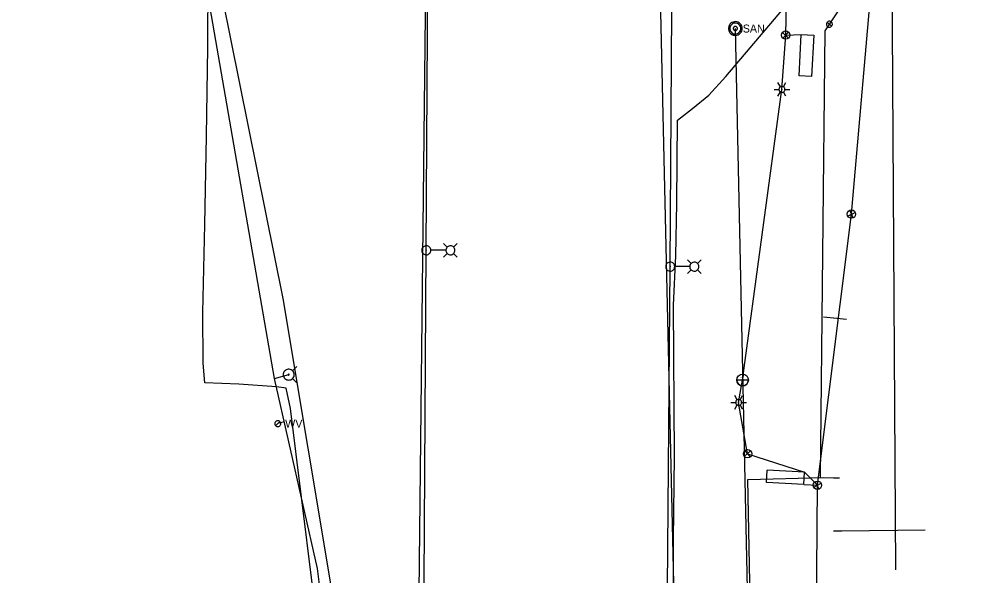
# Model space of a CAD drawing. Extents: x 600849 to 606371, y 330010 to 403088.
# Drawn here: x 604685.3 to 605141.7, y 332364 to 332631.5 of the extents above; entities that cross this region are included whole.
import ezdxf

# ---------------------------------------------------------------- set-up
doc = ezdxf.new("R2010")
doc.units = 0
for name, color, linetype in [('E_FTMS_Conduit', 7, 'Continuous'), ('E_LTG', 7, 'Continuous'), ('E_LTG_CID', 7, 'Continuous'), ('E_SIG', 7, 'Continuous'), ('E_SIG_Conduit', 7, 'Continuous'), ('E_UTL_E_UG', 7, 'Continuous'), ('E_UTL_G_UG', 7, 'Continuous'), ('E_UTL_Loop_UG', 7, 'Continuous'), ('E_UTL_SAN', 7, 'Continuous'), ('E_UTL_SAN_UG', 7, 'Continuous'), ('E_UTL_SAN_UG_MMSD', 7, 'Continuous'), ('E_UTL_W', 7, 'Continuous'), ('E_UTL_W_UG', 7, 'Continuous'), ('E_UTL_WHydrant', 7, 'Continuous')]:
    doc.layers.add(name, color=color, linetype=linetype)

# ---------------------------------------------------------------- blocks, each defined once
blk = doc.blocks.new('_U297')
at = {"layer": 'E_LTG'}
blk.add_lwpolyline([(0.001, -0.171), (0.001, 0.172)], dxfattribs=at)
blk.add_circle((0.001, 0), 0.171, dxfattribs=at)
blk.add_arc((0.001, 0), 0.171, 90, 270, dxfattribs=at)
blk.add_text('L', height=0.108, dxfattribs=at).set_placement((0.066, -0.042))
blk = doc.blocks.new('_U298')
at = {"layer": 'E_SIG'}
for p, q in [((-6.1, 0.4), (6.1, 0.4)), ((0, 6.1), (0, -6.1))]:
    blk.add_line(p, q, dxfattribs=at)
blk.add_circle((0, 0), 6.1, dxfattribs=at)
blk = doc.blocks.new('_U311')
at = {"layer": 'E_SIG'}
for p, q in [((-6.1, 0.4), (6.1, 0.4)), ((0, 6.1), (0, -6.1))]:
    blk.add_line(p, q, dxfattribs=at)
blk.add_circle((0, 0), 6.1, dxfattribs=at)
blk = doc.blocks.new('_U312')
at = {"layer": 'E_SIG'}
for p, q in [((-6.1, 0.4), (6.1, 0.4)), ((0, 6.1), (0, -6.1))]:
    blk.add_line(p, q, dxfattribs=at)
blk.add_circle((0, 0), 6.1, dxfattribs=at)
blk = doc.blocks.new('_U313')
at = {"layer": 'E_SIG'}
for p, q in [((-6.1, 0.4), (6.1, 0.4)), ((0, 6.1), (0, -6.1))]:
    blk.add_line(p, q, dxfattribs=at)
blk.add_circle((0, 0), 6.1, dxfattribs=at)

msp = doc.modelspace()

# ---------------------------------------------------------------- linework, layer by layer
at = {"layer": 'E_FTMS_Conduit'}
msp.add_lwpolyline([(604875.48, 332151.89), (604882.43, 332779.77)], dxfattribs=at)
at = {"layer": 'E_LTG'}
for points in [[(605051.51, 332598.97), (605050.32, 332601.03)], [(605052.94, 332598.97), (605054.13, 332601.03)], [(605048.42, 332597.73), (605050.8, 332597.73)], [(605050.32, 332594.43), (605051.51, 332596.49)], [(605053.66, 332597.73), (605053.63, 332598), (605053.55, 332598.26), (605053.43, 332598.5), (605053.26, 332598.72), (605053.06, 332598.89), (605052.82, 332599.03), (605052.56, 332599.12), (605052.29, 332599.16), (605052.02, 332599.15), (605051.76, 332599.08), (605051.51, 332598.97), (605051.29, 332598.81), (605051.1, 332598.61), (605050.96, 332598.39), (605050.86, 332598.13), (605050.8, 332597.87), (605050.8, 332597.59), (605050.86, 332597.33), (605050.96, 332597.08), (605051.1, 332596.85), (605051.29, 332596.65), (605051.51, 332596.49), (605051.76, 332596.38), (605052.02, 332596.32), (605052.29, 332596.3), (605052.56, 332596.34), (605052.82, 332596.43), (605053.06, 332596.57), (605053.26, 332596.74), (605053.43, 332596.96), (605053.55, 332597.2), (605053.63, 332597.46), (605053.66, 332597.73)], [(605053.66, 332597.73), (605053.63, 332598), (605053.55, 332598.26), (605053.43, 332598.5), (605053.26, 332598.72), (605053.06, 332598.89), (605052.82, 332599.03), (605052.56, 332599.12), (605052.29, 332599.16), (605052.02, 332599.15), (605051.76, 332599.08), (605051.51, 332598.97), (605051.29, 332598.81), (605051.1, 332598.61), (605050.96, 332598.39), (605050.86, 332598.13), (605050.8, 332597.87), (605050.8, 332597.59), (605050.86, 332597.33), (605050.96, 332597.08), (605051.1, 332596.85), (605051.29, 332596.65), (605051.51, 332596.49), (605051.76, 332596.38), (605052.02, 332596.32), (605052.29, 332596.3), (605052.56, 332596.34), (605052.82, 332596.43), (605053.06, 332596.57), (605053.26, 332596.74), (605053.43, 332596.96), (605053.55, 332597.2), (605053.63, 332597.46), (605053.66, 332597.73)], [(605053.66, 332597.73), (605053.63, 332598), (605053.55, 332598.26), (605053.43, 332598.5), (605053.26, 332598.72), (605053.06, 332598.89), (605052.82, 332599.03), (605052.56, 332599.12), (605052.29, 332599.16), (605052.02, 332599.15), (605051.76, 332599.08), (605051.51, 332598.97), (605051.29, 332598.81), (605051.1, 332598.61), (605050.96, 332598.39), (605050.86, 332598.13), (605050.8, 332597.87), (605050.8, 332597.59), (605050.86, 332597.33), (605050.96, 332597.08), (605051.1, 332596.85), (605051.29, 332596.65), (605051.51, 332596.49), (605051.76, 332596.38), (605052.02, 332596.32), (605052.29, 332596.3), (605052.56, 332596.34), (605052.82, 332596.43), (605053.06, 332596.57), (605053.26, 332596.74), (605053.43, 332596.96), (605053.55, 332597.2), (605053.63, 332597.46), (605053.66, 332597.73)], [(605052.35, 332597.73), (605052.34, 332597.75), (605052.34, 332597.78), (605052.33, 332597.8), (605052.31, 332597.81), (605052.3, 332597.83), (605052.28, 332597.84), (605052.25, 332597.85), (605052.23, 332597.85), (605052.21, 332597.85), (605052.19, 332597.84), (605052.17, 332597.83), (605052.15, 332597.82), (605052.13, 332597.8), (605052.12, 332597.79), (605052.11, 332597.76), (605052.11, 332597.74), (605052.11, 332597.72), (605052.11, 332597.7), (605052.12, 332597.68), (605052.13, 332597.66), (605052.15, 332597.64), (605052.17, 332597.63), (605052.19, 332597.62), (605052.21, 332597.61), (605052.23, 332597.61), (605052.25, 332597.62), (605052.28, 332597.62), (605052.3, 332597.63), (605052.31, 332597.65), (605052.33, 332597.67), (605052.34, 332597.69), (605052.34, 332597.71), (605052.35, 332597.73)], [(605054.13, 332594.43), (605052.94, 332596.49)], [(605053.66, 332597.73), (605056.04, 332597.73)], [(604883.39, 332520.43), (604883.35, 332520.85), (604883.23, 332521.24), (604883.04, 332521.61), (604882.78, 332521.94), (604882.47, 332522.21), (604882.11, 332522.41), (604881.72, 332522.55), (604881.31, 332522.61), (604880.9, 332522.59), (604880.5, 332522.49), (604880.12, 332522.32), (604879.79, 332522.08), (604879.5, 332521.78), (604879.28, 332521.43), (604879.12, 332521.05), (604879.04, 332520.64), (604879.04, 332520.23), (604879.12, 332519.82), (604879.28, 332519.44), (604879.5, 332519.09), (604879.79, 332518.79), (604880.12, 332518.55), (604880.5, 332518.38), (604880.9, 332518.28), (604881.31, 332518.26), (604881.72, 332518.32), (604882.11, 332518.45), (604882.47, 332518.66), (604882.78, 332518.93), (604883.04, 332519.26), (604883.23, 332519.63), (604883.35, 332520.02), (604883.39, 332520.43)], [(604891.29, 332521.96), (604889.51, 332523.73)], [(604894.99, 332520.43), (604894.95, 332520.85), (604894.83, 332521.24), (604894.64, 332521.61), (604894.39, 332521.94), (604894.08, 332522.21), (604893.72, 332522.41), (604893.33, 332522.55), (604892.92, 332522.61), (604892.5, 332522.59), (604892.1, 332522.49), (604891.73, 332522.32), (604891.39, 332522.08), (604891.1, 332521.78), (604890.88, 332521.43), (604890.73, 332521.05), (604890.65, 332520.64), (604890.65, 332520.23), (604890.73, 332519.82), (604890.88, 332519.44), (604891.1, 332519.09), (604891.39, 332518.79), (604891.73, 332518.55), (604892.1, 332518.38), (604892.5, 332518.28), (604892.92, 332518.26), (604893.33, 332518.32), (604893.72, 332518.45), (604894.08, 332518.66), (604894.39, 332518.93), (604894.64, 332519.26), (604894.83, 332519.63), (604894.95, 332520.02), (604894.99, 332520.43)], [(604894.34, 332521.96), (604896.11, 332523.73)], [(604881.38, 332520.43), (604881.37, 332520.47), (604881.36, 332520.5), (604881.35, 332520.52), (604881.33, 332520.55), (604881.31, 332520.57), (604881.28, 332520.59), (604881.25, 332520.6), (604881.22, 332520.6), (604881.19, 332520.6), (604881.16, 332520.59), (604881.13, 332520.58), (604881.1, 332520.56), (604881.08, 332520.54), (604881.06, 332520.51), (604881.05, 332520.48), (604881.04, 332520.45), (604881.04, 332520.42), (604881.05, 332520.39), (604881.06, 332520.36), (604881.08, 332520.33), (604881.1, 332520.31), (604881.13, 332520.29), (604881.16, 332520.28), (604881.19, 332520.27), (604881.22, 332520.27), (604881.25, 332520.27), (604881.28, 332520.28), (604881.31, 332520.3), (604881.33, 332520.32), (604881.35, 332520.34), (604881.36, 332520.37), (604881.37, 332520.4), (604881.38, 332520.43)], [(604890.6, 332520.43), (604883.42, 332520.43)], [(604891.29, 332518.91), (604889.51, 332517.13)], [(604894.34, 332518.91), (604896.11, 332517.13)], [(605000.66, 332512.59), (605000.62, 332513), (605000.51, 332513.4), (605000.32, 332513.77), (605000.06, 332514.09), (604999.75, 332514.36), (604999.39, 332514.57), (604999, 332514.71), (604998.59, 332514.76), (604998.18, 332514.74), (604997.78, 332514.65), (604997.4, 332514.48), (604997.06, 332514.24), (604996.78, 332513.94), (604996.55, 332513.59), (604996.4, 332513.2), (604996.32, 332512.8), (604996.32, 332512.38), (604996.4, 332511.98), (604996.55, 332511.59), (604996.78, 332511.25), (604997.06, 332510.95), (604997.4, 332510.71), (604997.78, 332510.53), (604998.18, 332510.44), (604998.59, 332510.42), (604999, 332510.48), (604999.39, 332510.61), (604999.75, 332510.82), (605000.06, 332511.09), (605000.32, 332511.41), (605000.51, 332511.78), (605000.62, 332512.18), (605000.66, 332512.59)], [(605008.57, 332514.12), (605006.79, 332515.89)], [(605012.27, 332512.59), (605012.23, 332513), (605012.11, 332513.4), (605011.92, 332513.77), (605011.66, 332514.09), (605011.35, 332514.36), (605010.99, 332514.57), (605010.6, 332514.71), (605010.19, 332514.76), (605009.78, 332514.74), (605009.38, 332514.65), (605009, 332514.48), (605008.67, 332514.24), (605008.38, 332513.94), (605008.16, 332513.59), (605008, 332513.2), (605007.92, 332512.8), (605007.92, 332512.38), (605008, 332511.98), (605008.16, 332511.59), (605008.38, 332511.25), (605008.67, 332510.95), (605009, 332510.71), (605009.38, 332510.53), (605009.78, 332510.44), (605010.19, 332510.42), (605010.6, 332510.48), (605010.99, 332510.61), (605011.35, 332510.82), (605011.66, 332511.09), (605011.92, 332511.41), (605012.11, 332511.78), (605012.23, 332512.18), (605012.27, 332512.59)], [(605011.62, 332514.12), (605013.39, 332515.89)], [(604998.65, 332512.59), (604998.65, 332512.62), (604998.64, 332512.65), (604998.63, 332512.68), (604998.61, 332512.71), (604998.58, 332512.73), (604998.56, 332512.74), (604998.53, 332512.75), (604998.49, 332512.76), (604998.46, 332512.76), (604998.43, 332512.75), (604998.4, 332512.74), (604998.38, 332512.72), (604998.36, 332512.69), (604998.34, 332512.67), (604998.33, 332512.64), (604998.32, 332512.61), (604998.32, 332512.58), (604998.33, 332512.54), (604998.34, 332512.51), (604998.36, 332512.49), (604998.38, 332512.47), (604998.4, 332512.45), (604998.43, 332512.43), (604998.46, 332512.43), (604998.49, 332512.42), (604998.53, 332512.43), (604998.56, 332512.44), (604998.58, 332512.46), (604998.61, 332512.48), (604998.63, 332512.5), (604998.64, 332512.53), (604998.65, 332512.56), (604998.65, 332512.59)], [(605007.88, 332512.59), (605000.7, 332512.59)], [(605008.57, 332511.07), (605006.79, 332509.29)], [(605011.62, 332511.07), (605013.39, 332509.29)], [(605030.68, 332448.61), (605029.49, 332450.67)], [(605032.11, 332448.61), (605033.3, 332450.67)], [(605027.58, 332447.37), (605029.96, 332447.37)], [(605029.49, 332444.07), (605030.68, 332446.13)], [(605032.82, 332447.37), (605032.8, 332447.64), (605032.72, 332447.9), (605032.6, 332448.14), (605032.43, 332448.35), (605032.22, 332448.53), (605031.99, 332448.67), (605031.73, 332448.76), (605031.46, 332448.8), (605031.19, 332448.78), (605030.93, 332448.72), (605030.68, 332448.61), (605030.46, 332448.45), (605030.27, 332448.25), (605030.12, 332448.02), (605030.02, 332447.77), (605029.97, 332447.5), (605029.97, 332447.23), (605030.02, 332446.97), (605030.12, 332446.71), (605030.27, 332446.48), (605030.46, 332446.29), (605030.68, 332446.13), (605030.93, 332446.02), (605031.19, 332445.95), (605031.46, 332445.94), (605031.73, 332445.98), (605031.99, 332446.07), (605032.22, 332446.2), (605032.43, 332446.38), (605032.6, 332446.6), (605032.72, 332446.84), (605032.8, 332447.1), (605032.82, 332447.37)], [(605032.82, 332447.37), (605032.8, 332447.64), (605032.72, 332447.9), (605032.6, 332448.14), (605032.43, 332448.35), (605032.22, 332448.53), (605031.99, 332448.67), (605031.73, 332448.76), (605031.46, 332448.8), (605031.19, 332448.78), (605030.93, 332448.72), (605030.68, 332448.61), (605030.46, 332448.45), (605030.27, 332448.25), (605030.12, 332448.02), (605030.02, 332447.77), (605029.97, 332447.5), (605029.97, 332447.23), (605030.02, 332446.97), (605030.12, 332446.71), (605030.27, 332446.48), (605030.46, 332446.29), (605030.68, 332446.13), (605030.93, 332446.02), (605031.19, 332445.95), (605031.46, 332445.94), (605031.73, 332445.98), (605031.99, 332446.07), (605032.22, 332446.2), (605032.43, 332446.38), (605032.6, 332446.6), (605032.72, 332446.84), (605032.8, 332447.1), (605032.82, 332447.37)], [(605032.82, 332447.37), (605032.8, 332447.64), (605032.72, 332447.9), (605032.6, 332448.14), (605032.43, 332448.35), (605032.22, 332448.53), (605031.99, 332448.67), (605031.73, 332448.76), (605031.46, 332448.8), (605031.19, 332448.78), (605030.93, 332448.72), (605030.68, 332448.61), (605030.46, 332448.45), (605030.27, 332448.25), (605030.12, 332448.02), (605030.02, 332447.77), (605029.97, 332447.5), (605029.97, 332447.23), (605030.02, 332446.97), (605030.12, 332446.71), (605030.27, 332446.48), (605030.46, 332446.29), (605030.68, 332446.13), (605030.93, 332446.02), (605031.19, 332445.95), (605031.46, 332445.94), (605031.73, 332445.98), (605031.99, 332446.07), (605032.22, 332446.2), (605032.43, 332446.38), (605032.6, 332446.6), (605032.72, 332446.84), (605032.8, 332447.1), (605032.82, 332447.37)], [(605031.51, 332447.37), (605031.51, 332447.39), (605031.5, 332447.41), (605031.49, 332447.43), (605031.48, 332447.45), (605031.46, 332447.47), (605031.44, 332447.48), (605031.42, 332447.48), (605031.4, 332447.49), (605031.38, 332447.49), (605031.35, 332447.48), (605031.33, 332447.47), (605031.32, 332447.46), (605031.3, 332447.44), (605031.29, 332447.42), (605031.28, 332447.4), (605031.28, 332447.38), (605031.28, 332447.36), (605031.28, 332447.33), (605031.29, 332447.31), (605031.3, 332447.29), (605031.32, 332447.28), (605031.33, 332447.26), (605031.35, 332447.26), (605031.38, 332447.25), (605031.4, 332447.25), (605031.42, 332447.25), (605031.44, 332447.26), (605031.46, 332447.27), (605031.48, 332447.29), (605031.49, 332447.3), (605031.5, 332447.32), (605031.51, 332447.35), (605031.51, 332447.37)], [(605033.3, 332444.07), (605032.11, 332446.13)], [(605032.82, 332447.37), (605035.2, 332447.37)]]:
    msp.add_lwpolyline(points, dxfattribs=at)
at = {"layer": 'E_LTG_CID'}
for points in [[(604879.6, 332255.02), (604881.21, 332520.43), (604882.73, 332780.27), (604878.2, 332790.52), (604877.91, 332791.78), (604881.34, 332802.26), (604883.13, 332854.03), (604882.52, 332888.97), (604884.51, 332915.54), (604885.08, 332965.87), (604885.55, 333001.94), (604887.55, 333053.11), (604887.38, 333057.43), (604890.09, 333114.03), (604893.58, 333149.05), (604892.31, 333167.75), (604894.55, 333225.52), (604896.01, 333258.34), (604895.95, 333311.87), (604895.91, 333311.87), (604896.37, 333313.71), (604895.92, 333323.72), (604897.23, 333357.63), (604900.28, 333466.82)], [(604931.85, 331581.07), (604937.27, 331603.67), (604947.8, 331650.94), (604952, 331678.28), (604955.83, 331701.76), (604989.48, 331966.47), (604996.27, 332242.26), (604998.49, 332512.59), (605000.29, 332783.81), (605002.15, 332931.75), (605000.64, 332964.83), (605000.69, 332966.2), (605002.17, 333011.44), (605003.78, 333073.37), (605005.15, 333128.46), (605004.43, 333142.5)], [(605033.31, 332458.1), (605052.23, 332597.73), (605054.03, 332623.78)], [(605035.68, 332422.67), (605031.39, 332447.37), (605033.31, 332458.1)]]:
    msp.add_lwpolyline(points, dxfattribs=at)
at = {"layer": 'E_SIG_Conduit'}
for p, q in [((605044.84, 332408.89), (605045.16, 332414.88)), ((605063.14, 332413.92), (605045.16, 332414.88)), ((605062.82, 332407.93), (605063.14, 332413.92)), ((605062.82, 332407.93), (605044.84, 332408.89)), ((605062.82, 332407.93), (605069.29, 332407.59))]:
    msp.add_line(p, q, dxfattribs=at)
for points in [[(605035.68, 332422.67), (605063.14, 332413.92), (605069.29, 332407.59), (605085.64, 332537.82), (605096.42, 332660.59)], [(605054.03, 332623.78), (605054.73, 332656.67), (605054.68, 332659.2)]]:
    msp.add_lwpolyline(points, dxfattribs=at)
at = {"layer": 'E_UTL_E_UG'}
msp.add_lwpolyline([(605060.47, 331707.24), (605067.75, 331788.52), (605068.77, 331809.24), (605068.42, 331863), (605066.58, 332057.11), (605069.29, 332407.59)], dxfattribs=at)
at = {"layer": 'E_UTL_G_UG'}
for points in [[(604826.46, 332359.31), (604815.87, 332444.5), (604813.9, 332454.28), (604809.14, 332454.89), (604791.01, 332456.14), (604774.74, 332456.76), (604773.86, 332466.27), (604773.81, 332490.55), (604774.78, 332532.83), (604775.53, 332575.18), (604776.11, 332617.83), (604776.51, 332684.21)], [(605106.93, 332366.96), (605105.02, 332679.56)], [(605000.09, 332338.31), (605000.11, 332381.53), (605000.58, 332421.33), (605000.12, 332494.14), (605001.25, 332517.82), (605001.72, 332543.05), (605001.99, 332582.9), (605009.14, 332588.51), (605017.08, 332595.02), (605025.17, 332603.98), (605053.2, 332636.73), (605068.82, 332651.42), (605069.91, 332651.64), (605092.37, 332651), (605098.99, 332656), (605103.96, 332660.87), (605106.76, 332663.11), (605116.6, 332673.18), (605136.39, 332673.6), (605163.97, 332673.14), (605215.25, 332672.77), (605447.16, 332669.14)], [(605077.01, 332385.6), (605081, 332385.66)], [(605081, 332385.66), (605121.14, 332386.18)]]:
    msp.add_lwpolyline(points, dxfattribs=at)
at = {"layer": 'E_UTL_Loop_UG'}
msp.add_line((605054.03, 332623.78), (605061.51, 332624.16), dxfattribs=at)
msp.add_lwpolyline([(605061.51, 332624.16), (605067.5, 332623.85), (605066.5, 332603.88), (605060.51, 332604.18), (605061.51, 332624.16)], dxfattribs=at)
at = {"layer": 'E_UTL_SAN'}
for points in [[(605033.1, 332626.97), (605033.04, 332627.59), (605032.87, 332628.19), (605032.58, 332628.75), (605032.19, 332629.25), (605031.72, 332629.66), (605031.17, 332629.97), (605030.58, 332630.17), (605029.96, 332630.26), (605029.33, 332630.23), (605028.72, 332630.09), (605028.15, 332629.83), (605027.64, 332629.46), (605027.21, 332629.01), (605026.87, 332628.48), (605026.64, 332627.9), (605026.52, 332627.28), (605026.52, 332626.65), (605026.64, 332626.04), (605026.87, 332625.46), (605027.21, 332624.93), (605027.64, 332624.47), (605028.15, 332624.11), (605028.72, 332623.85), (605029.33, 332623.7), (605029.96, 332623.67), (605030.58, 332623.76), (605031.17, 332623.97), (605031.72, 332624.28), (605032.19, 332624.69), (605032.58, 332625.18), (605032.87, 332625.74), (605033.04, 332626.34), (605033.1, 332626.97)], [(605032.44, 332626.97), (605032.39, 332627.47), (605032.25, 332627.95), (605032.02, 332628.4), (605031.71, 332628.79), (605031.33, 332629.12), (605030.9, 332629.37), (605030.43, 332629.53), (605029.93, 332629.6), (605029.43, 332629.58), (605028.94, 332629.46), (605028.48, 332629.25), (605028.07, 332628.96), (605027.73, 332628.6), (605027.46, 332628.18), (605027.27, 332627.71), (605027.17, 332627.22), (605027.17, 332626.72), (605027.27, 332626.22), (605027.46, 332625.76), (605027.73, 332625.34), (605028.07, 332624.97), (605028.48, 332624.68), (605028.94, 332624.47), (605029.43, 332624.35), (605029.93, 332624.33), (605030.43, 332624.4), (605030.9, 332624.57), (605031.33, 332624.82), (605031.71, 332625.15), (605032.02, 332625.54), (605032.25, 332625.99), (605032.39, 332626.47), (605032.44, 332626.97)], [(605030.79, 332626.97), (605030.77, 332627.16), (605030.72, 332627.34), (605030.64, 332627.5), (605030.52, 332627.65), (605030.38, 332627.77), (605030.21, 332627.87), (605030.04, 332627.93), (605029.85, 332627.96), (605029.66, 332627.95), (605029.48, 332627.9), (605029.31, 332627.83), (605029.15, 332627.72), (605029.02, 332627.58), (605028.92, 332627.42), (605028.85, 332627.25), (605028.82, 332627.06), (605028.82, 332626.87), (605028.85, 332626.69), (605028.92, 332626.51), (605029.02, 332626.36), (605029.15, 332626.22), (605029.31, 332626.11), (605029.48, 332626.03), (605029.66, 332625.99), (605029.85, 332625.98), (605030.04, 332626.01), (605030.21, 332626.07), (605030.38, 332626.16), (605030.52, 332626.28), (605030.64, 332626.43), (605030.72, 332626.6), (605030.77, 332626.78), (605030.79, 332626.97)]]:
    msp.add_lwpolyline(points, dxfattribs=at)
at = {"layer": 'E_UTL_SAN_UG'}
msp.add_line((605035.68, 332357.68), (605029.94, 332626.92), dxfattribs=at)
at = {"layer": 'E_UTL_SAN_UG_MMSD'}
msp.add_line((605001.66, 332297.25), (604992.09, 332721.29), dxfattribs=at)
at = {"layer": 'E_UTL_W'}
for points in [[(605075.05, 332630.46), (605074.78, 332630.43), (605074.52, 332630.36), (605074.27, 332630.23), (605074.06, 332630.06), (605073.88, 332629.86), (605073.75, 332629.63), (605073.66, 332629.37), (605073.62, 332629.1), (605073.63, 332628.83), (605073.7, 332628.57), (605073.81, 332628.32), (605073.97, 332628.1), (605074.16, 332627.91), (605074.39, 332627.77), (605074.64, 332627.66), (605074.91, 332627.61), (605075.18, 332627.61), (605075.45, 332627.66), (605075.7, 332627.77), (605075.93, 332627.91), (605076.12, 332628.1), (605076.28, 332628.32), (605076.39, 332628.57), (605076.46, 332628.83), (605076.47, 332629.1), (605076.43, 332629.37), (605076.34, 332629.63), (605076.21, 332629.86), (605076.03, 332630.06), (605075.82, 332630.23), (605075.58, 332630.36), (605075.32, 332630.43), (605075.05, 332630.46)], [(605076.05, 332628.02), (605074.04, 332630.04)], [(604811.21, 332437.17), (604811.18, 332437.44), (604811.1, 332437.7), (604810.98, 332437.94), (604810.81, 332438.15), (604810.61, 332438.33), (604810.37, 332438.46), (604810.12, 332438.55), (604809.85, 332438.59), (604809.58, 332438.58), (604809.31, 332438.51), (604809.07, 332438.4), (604808.85, 332438.24), (604808.66, 332438.05), (604808.51, 332437.82), (604808.41, 332437.57), (604808.36, 332437.3), (604808.36, 332437.03), (604808.41, 332436.76), (604808.51, 332436.51), (604808.66, 332436.28), (604808.85, 332436.09), (604809.07, 332435.93), (604809.31, 332435.82), (604809.58, 332435.75), (604809.85, 332435.74), (604810.12, 332435.78), (604810.37, 332435.87), (604810.61, 332436), (604810.81, 332436.18), (604810.98, 332436.39), (604811.1, 332436.64), (604811.18, 332436.9), (604811.21, 332437.17)], [(604808.77, 332436.16), (604810.79, 332438.17)]]:
    msp.add_lwpolyline(points, dxfattribs=at)
at = {"layer": 'E_UTL_W_UG'}
for p, q in [((604812.41, 332497.24), (604779.77, 332658.55)), ((605070.68, 332411.27), (605072.97, 332625.93)), ((604848.64, 332280.87), (604812.41, 332497.24)), ((604812.41, 332497.24), (604812.41, 332497.24)), ((604808.28, 332458.89), (604815.05, 332460.7)), ((604828.93, 332367.61), (604808.28, 332458.89)), ((604839.02, 332287.19), (604828.93, 332367.61))]:
    msp.add_line(p, q, dxfattribs=at)
for points in [[(605072.97, 332625.93), (605099.78, 332666.04)], [(604808.28, 332458.89), (604777.25, 332636.97), (604777.25, 332650.97)], [(605083.19, 332487.13), (605078.56, 332487.66), (605072.22, 332488.31)], [(604813.01, 332438), (604809.78, 332437.17)], [(604662.85, 330776.78), (604719.99, 330861.17), (604771.51, 330900.13), (604792.62, 330926.22), (604804.59, 330947.13), (605054.68, 331381.7), (605055.13, 331442.45), (605044.65, 331474.36), (605047.01, 331851.63), (605038.36, 332278.66), (605035.8, 332410.28), (605072.23, 332411.32), (605076.98, 332411.12), (605079.88, 332411.16)]]:
    msp.add_lwpolyline(points, dxfattribs=at)
at = {"layer": 'E_UTL_WHydrant'}
for points in [[(604815.05, 332458.08), (604815.55, 332458.13), (604816.03, 332458.27), (604816.47, 332458.5), (604816.86, 332458.81), (604817.19, 332459.18), (604817.44, 332459.61), (604817.6, 332460.09), (604817.67, 332460.58), (604817.65, 332461.08), (604817.53, 332461.56), (604817.33, 332462.02), (604817.04, 332462.42), (604816.68, 332462.77), (604816.26, 332463.04), (604815.79, 332463.22), (604815.3, 332463.32), (604814.81, 332463.32), (604814.32, 332463.22), (604813.85, 332463.04), (604813.43, 332462.77), (604813.07, 332462.42), (604812.78, 332462.02), (604812.58, 332461.56), (604812.46, 332461.08), (604812.43, 332460.58), (604812.51, 332460.09), (604812.67, 332459.61), (604812.92, 332459.18), (604813.24, 332458.81), (604813.64, 332458.5), (604814.08, 332458.27), (604814.56, 332458.13), (604815.05, 332458.08)], [(604816.89, 332462.54), (604819.03, 332464.68)], [(604815.05, 332460.5), (604815.09, 332460.51), (604815.13, 332460.52), (604815.16, 332460.54), (604815.19, 332460.56), (604815.22, 332460.59), (604815.24, 332460.62), (604815.25, 332460.66), (604815.25, 332460.69), (604815.25, 332460.73), (604815.24, 332460.77), (604815.23, 332460.8), (604815.21, 332460.84), (604815.18, 332460.86), (604815.15, 332460.88), (604815.11, 332460.9), (604815.07, 332460.9), (604815.04, 332460.9), (604815, 332460.9), (604814.96, 332460.88), (604814.93, 332460.86), (604814.9, 332460.84), (604814.88, 332460.8), (604814.87, 332460.77), (604814.86, 332460.73), (604814.85, 332460.69), (604814.86, 332460.66), (604814.87, 332460.62), (604814.89, 332460.59), (604814.92, 332460.56), (604814.95, 332460.54), (604814.98, 332460.52), (604815.02, 332460.51), (604815.05, 332460.5)], [(604816.89, 332458.87), (604819.03, 332456.73)]]:
    msp.add_lwpolyline(points, dxfattribs=at)

# ---------------------------------------------------------------- block references
at = {"layer": 'E_SIG'}
for name, p, xscale, yscale, rotation in [('_U298', (605054.03, 332623.78), 0.3280833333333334, 0.32808333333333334, 135.46812996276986), ('_U297', (605033.31, 332458.1), 16.40416666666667, 16.40416666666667, 89.99999999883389)]:
    msp.add_blockref(name, p, dxfattribs=dict(at, xscale=xscale, yscale=yscale, rotation=rotation))
at = {"layer": 'E_SIG_Conduit', "yscale": 0.32808333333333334}
for name, p, xscale, rotation in [('_U313', (605085.64, 332537.82), 0.3280833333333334, -155.07013962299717), ('_U312', (605035.68, 332422.67), 0.32808333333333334, 41.83625689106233), ('_U311', (605069.29, 332407.59), 0.32808333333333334, 118.0846575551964)]:
    msp.add_blockref(name, p, dxfattribs=dict(at, xscale=xscale, rotation=rotation))

# ---------------------------------------------------------------- texts
at = {"layer": 'E_UTL_SAN'}
msp.add_text('SAN', height=3.849, dxfattribs=at).set_placement((605033.37, 332625.02))
at = {"layer": 'E_UTL_W'}
msp.add_text('WV', height=3.85, dxfattribs=at).set_placement((604813.35, 332435.24))

doc.saveas('drawing.dxf')
